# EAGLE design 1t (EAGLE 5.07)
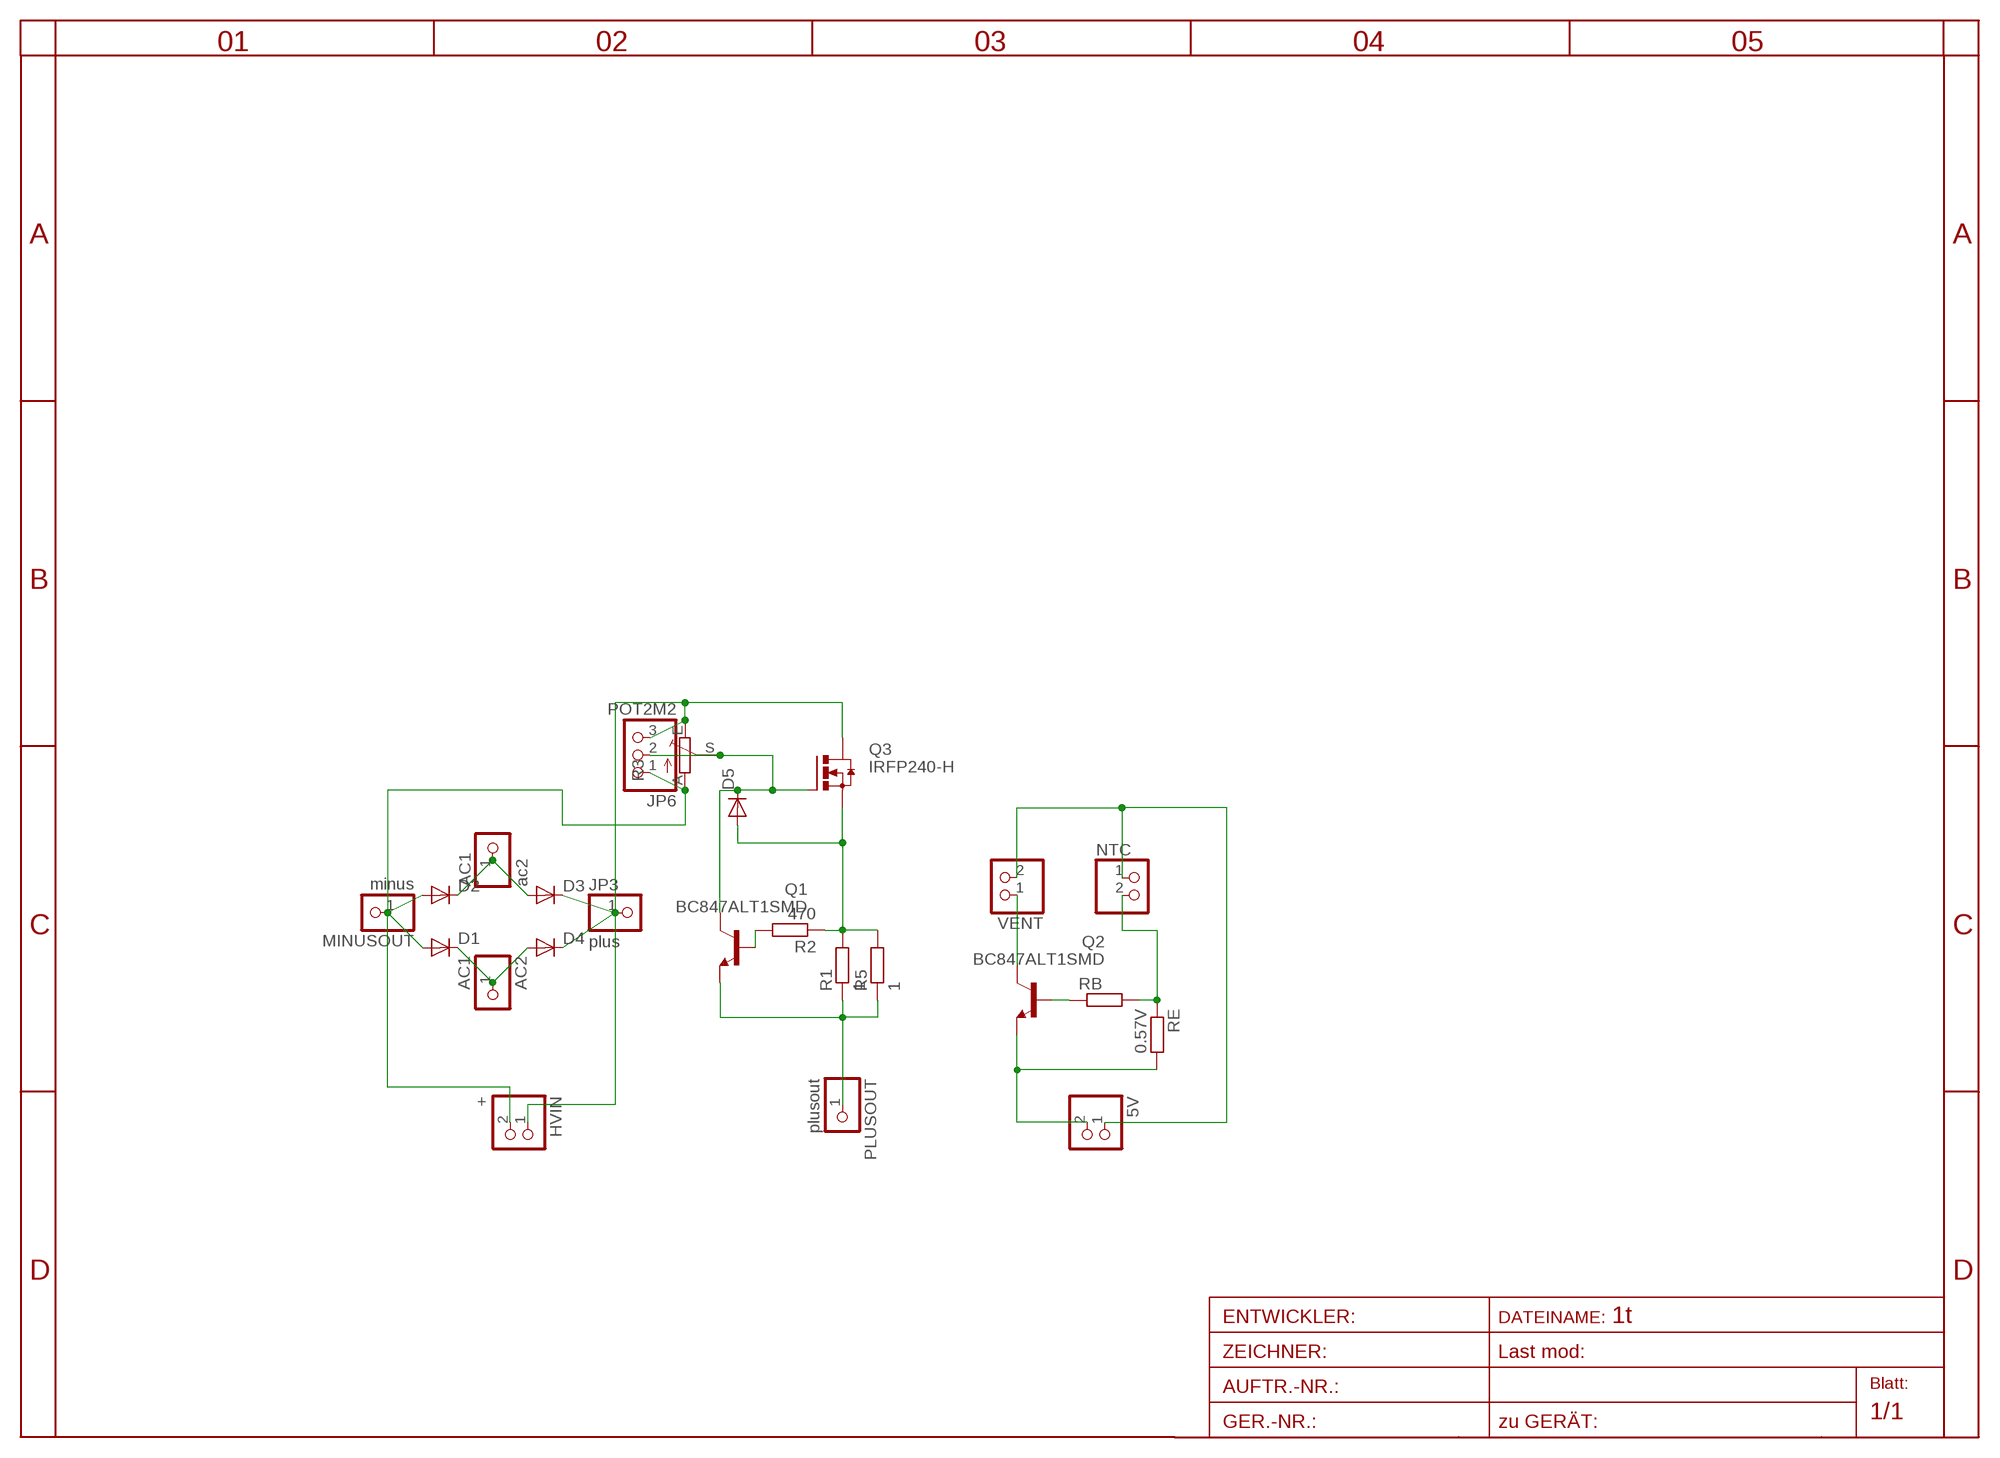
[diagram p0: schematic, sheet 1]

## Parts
5V  PINHD-1X2STR  [1X02]
AC1  ac2  PINHD-1X11MM0  [1X1MM0]
AC2  AC1  PINHD-1X11MM0  [1X1MM0]
D1  DIODE-SMB  [SMB]
D2  DIODE-SMB  [SMB]
D3  DIODE-SMB  [SMB]
D4  DIODE-SMB  [SMB]
D5  DIODE-MINIMELF  [MINIMELF]
HVIN  +  PINHD-1X2STR  [1X02]
JP3  plus  PINHD-1X11MM0  [1X1MM0]
JP6  POT2M2  PINHD-1X3  [1X03]
MINUSOUT  minus  PINHD-1X11MM0  [1X1MM0]
NTC  PINHD-1X2STR  [1X02]
PLUSOUT  plusout  PINHD-1X11MM0  [1X1MM0]
Q1  BC847ALT1SMD  [SOT23]
Q2  BC847ALT1SMD  [SOT23]
Q3  IRFP240-H  [TO247BH]
R1  1  R-EU_0207/10  [0207/10]
R2  470  R-EU_R0805  [R0805]
R3  TRIM_EU-CIP20C-6MM  [CIP20C-6MM]
R5  1  R-EU_R2010  [R2010]
RB  R-EU_R0805  [R0805]
RE  0.57V  R-EU_R0805  [R0805]
VENT  PINHD-1X2STR  [1X02]

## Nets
5V-: 5V.1 NTC.1 VENT.2
G: D5.C JP6.2 Q1.3(C) Q3.G R3.S
MINUS: D1.A D2.A HVIN.2 JP6.1 MINUSOUT.1 R3.A
N$3: AC1.1 D2.C D3.A
N$4: AC2.1 D1.C D4.A
N$6: Q1.1(B) R2.2
N$9: 5V.2 Q2.2(E) RE.2
N$10: Q2.1(B) RB.1
N$11: NTC.2 RB.2 RE.1
N$13: Q2.3(C) VENT.1
PLUS: D3.C D4.C HVIN.1 JP3.1 JP6.3 Q3.D R3.E
PLUSOUT: PLUSOUT.1 Q1.2(E) R1.1 R5.1
S: D5.A Q3.S R1.2 R2.1 R5.2

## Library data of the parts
5V HVIN NTC VENT = pinhead:PINHD-1X2: PIN HEADER
AC1 AC2 JP3 MINUSOUT PLUSOUT = pinhead:PINHD-1X1: PIN HEADER
D1-D5 = diode:DIODE-: DIODE
JP6 = pinhead:PINHD-1X3: PIN HEADER
Q1 Q2 = transistor-npn:BC847*: NPN Transistor
Q3 = transistor-power:IRFP240: HEXFET Power MosFet Source: http://www.irf.com/
R1 R2 R5 RB RE = rcl:R-EU_: RESISTOR, European symbol
R3 = pot:TRIM_EU-: POTENTIOMETER

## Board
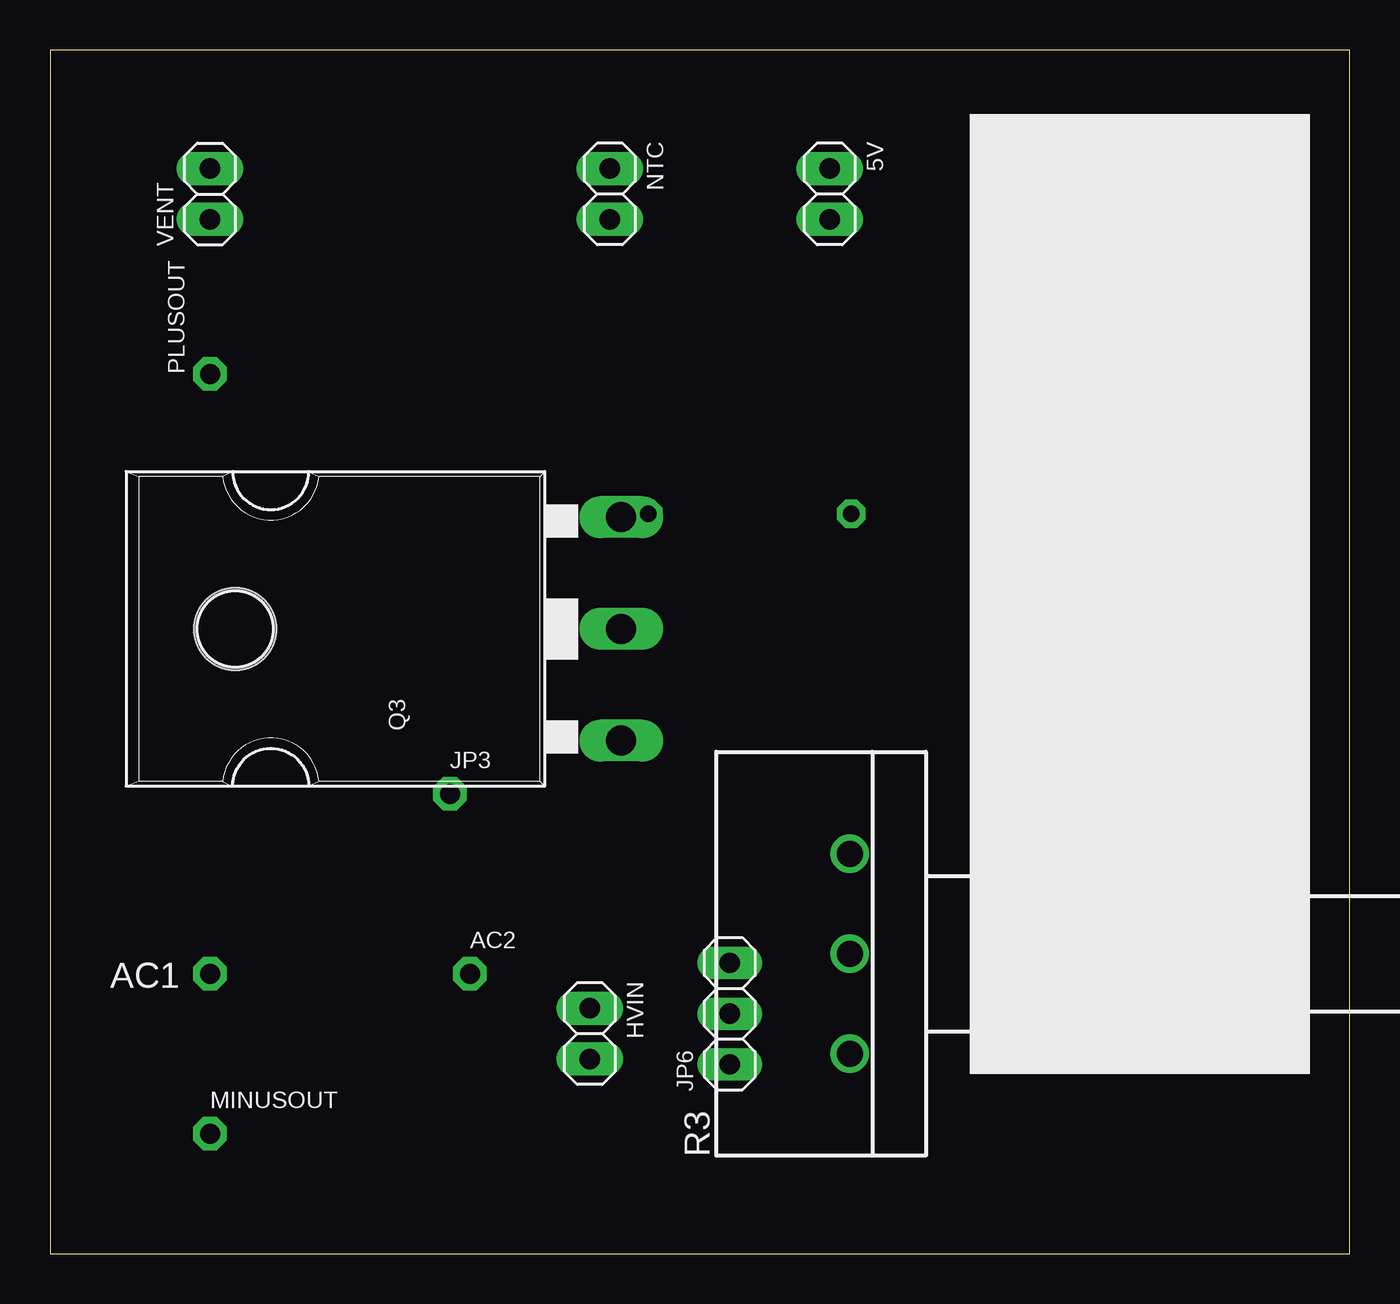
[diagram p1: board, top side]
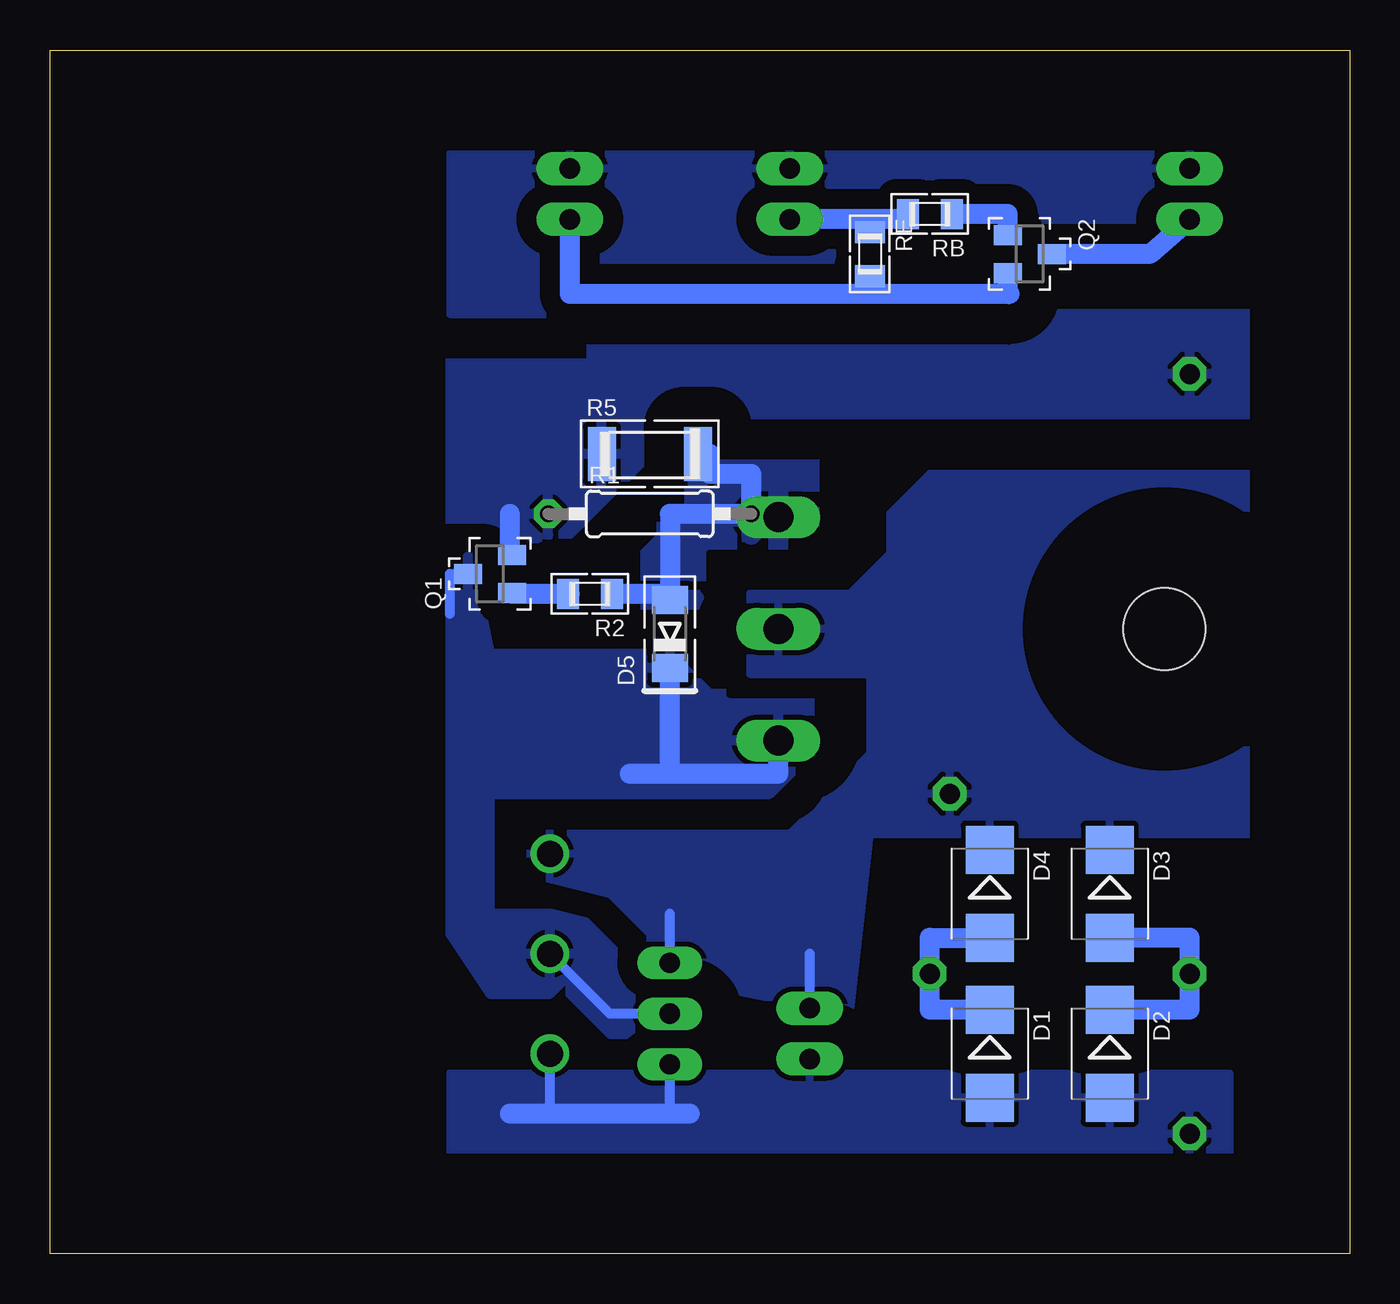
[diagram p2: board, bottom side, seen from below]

Size 65 x 60.2 mm. Coordinates in mm from the lower left corner, seen from the top.
Outline: 0,0 65,0 65,60.2 0,60.2 0,0
Copper layers (1*16): Top 0.035mm / dielectric 1.5mm / Bottom 0.035mm
Design rules "default *": minimum track width 10mil, minimum drill 20mil, track to track 8mil, track to pad 8mil, pad to pad 8mil, via to via 8mil, smd to smd 8mil, copper to edge 5mm, drill to drill 8mil, minimum pad ring 0.3mm, minimum via ring 8mil, stop-mask expansion 4mil, vias tented up to drill 0mil, thermal gap 10mil

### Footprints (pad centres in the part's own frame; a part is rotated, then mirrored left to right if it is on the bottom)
1X02 = drill 1.016 pad 1.676 long: 1 -1.27,0; 2 1.27,0
1X1MM0 = drill 1 pad 1.676 octagon: 1 0,0
SMB = smd 2.4 x 2.4: A 2.2,0; C -2.2,0
MINIMELF = smd 1.4 x 1.8: A 1.7,0; C -1.7,0
1X03 = drill 1.016 long: 1 -2.54,0; 2 0,0; 3 2.54,0
SOT23 = smd 1 x 1.4: 1 -0.95,-1.1; 2 0.95,-1.1; 3 0,1.1
TO247BH = drill 1.499 long: D 0,-10.16; G -5.588,-10.16; S 5.588,-10.16 | hole 4.115: 0,9.144
0207/10 = drill 0.813 octagon: 1 -5.08,0; 2 5.08,0
R0805 = smd 1.1 x 1.5: 1 -1.1,0; 2 1.1,0
CIP20C-6MM = drill 1.3 pad 1.93 round: A -5,0; E 5,0; S 0,0
R2010 = smd 1.4 x 2.7: 1 -2.4,0; 2 2.4,0

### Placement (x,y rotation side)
5V  39,53 270 top
AC1  8,14 0 top
AC2  21,14 0 top
D1  18,10 270 bottom
D2  12,10 270 bottom
D3  12,18 270 bottom
D4  18,18 270 bottom
D5  34,31 90 bottom
HVIN  27,11 270 top
JP3  20,23 0 top
JP6  34,12 90 top
MINUSOUT  8,6 0 top
NTC  28,53 270 top
PLUSOUT  8,44 90 top
Q1  43,34 90 bottom
Q2  16,50 270 bottom
Q3  18.41,31.24 90 top
R1  35,37 0 bottom
R2  38,33 180 bottom
R3  40,15 90 top
R5  35,40 0 bottom
RB  21,52 180 bottom
RE  24,50 270 bottom
VENT  8,53 90 top

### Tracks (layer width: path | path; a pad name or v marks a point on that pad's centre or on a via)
5V-
  pour Bottom (isolate 1): 7,56 42,56 45,55 45,47 7,47
G
  Bottom 0.5: JP6.2 37,12 R3.S | Q1.3 45,34 45,32
  Bottom 1: 34,24 28.57,24 Q3.G | 34,24 36,24 | 34,24 D5.C
  pour Bottom (isolate 1, rank 3): 44,35 45,34 45,16 43,13 40,13 39,14 39,13 37,11 34,11 33,12 33,13 34,13 38,17 43,17 43,23 29,23 27,25 27,28 32,28 34,30 43,30
MINUS
  Bottom 0.5: 40,7 R3.A | 34,7 JP6.1
  Bottom 1: 33,7 34,7 40,7 42,7
  pour Bottom (isolate 2): 6,9 45,9 45,4 7,3 6,4
N$3
  Bottom 1: D3.A 8,15.8 AC1.1 8,12.2 D2.C
N$4
  Bottom 1: D4.A 21,15.8 AC2.1 21,12.2 D1.C
N$6
  Bottom 1: 39,33 R2.2 41.9,33 Q1.1
N$9
  Bottom 1: 5V.2 39,48 24,48 | 17.1,48 24,48 | 17.1,48 17,48 | 17.1,48 Q2.2 | 24,48 RE.2
N$10
  Bottom 1: RB.1 17.1,52 Q2.1
N$11
  Bottom 1: 24,51.73 22.1,51.73 RB.2 | 24,51.73 NTC.2 | 24,51.73 RE.1
N$13
  Bottom 1: Q2.3 10,50 VENT.1
PLUS
  Bottom 0.5: HVIN.1 27,15 | JP6.3 34,17
  pour Bottom (isolate 2): 1,39 21,39 23,37 23,35 25,33 30,33 30,29 24,29 24,25 28,21 41,21 41,19 37,18 35,16 35,14 25,12 24,21 1,21
PLUSOUT
  Bottom 1: Q1.2 42,34.95 42,37
  pour Bottom (isolate 2, rank 2): 5,47 42,47 45,45 45,36 43,35 40,35 33,42 5,42
S
  Bottom 1: 34,33 R2.1 | 34,33 D5.A | R1.2 28.57,37 Q3.S | R5.2 32,40 32,39 29.92,39 R1.2 | R1.2 34,37 34,33
  pour Bottom (isolate 2, rank 3): 27,40 33,40 35,38 35,32 31,32 27,36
